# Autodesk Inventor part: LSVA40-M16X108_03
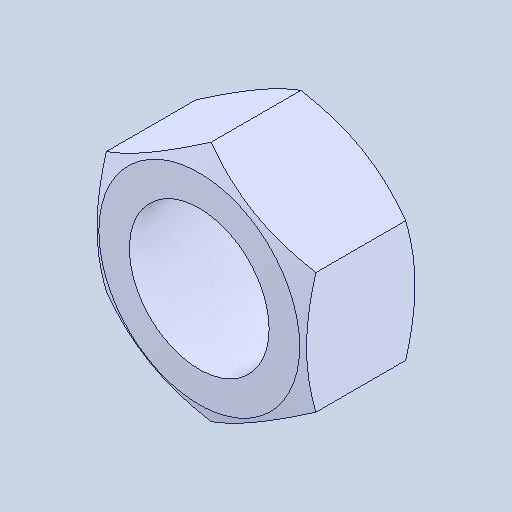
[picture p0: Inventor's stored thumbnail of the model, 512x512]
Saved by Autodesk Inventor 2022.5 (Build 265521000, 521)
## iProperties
Created: 2024-08
Part Number: LSVA40-M16X108_03
Material: 一般
Document SubType Name: Modeling
Designer: ImaoCorp
Density: 1 g/cm^3
Appearance: 既定
Author: ImaoCorp
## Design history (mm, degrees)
feature "LSVA40-M16X108_03"
node "ソリッド1"
